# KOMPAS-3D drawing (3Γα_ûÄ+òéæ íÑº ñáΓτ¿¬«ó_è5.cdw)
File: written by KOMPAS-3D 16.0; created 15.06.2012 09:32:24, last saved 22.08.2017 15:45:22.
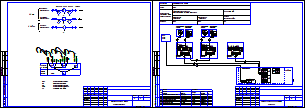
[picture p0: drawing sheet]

Sheets 1-2: A3, landscape

Title block, sheet 1: name: г. Москва, ул. Нежинская, д. 14, к.8 (кв. 1 и кв. 2); sheet number: 1; sheets: 27 / 28; sheet format: A3; stored path: D:\Проекты\Лыткарино\ул. Квартал 3А, д.25\710.74 РП.cdw; cell 320: Р
Title block, sheet 2: sheet number: 2

Views: Вид 2, Вид 3, Вид 4, Вид 5
Referenced files in C:\Program Files (x86)\ASCON\KOMPAS-3D V16\Sys\: SPDS.lcs, EngSys.lcs, GRAPHIC.LHS
Referenced files: graphic.tdp
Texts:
  МО, Клинский район, д. Решетниково, ул. Центральная, д.14
  GOST Common
  Normal
  List Paragraph
  heading 3
  для схемы
  txt
  краны
  Фоновая заливка
  Т0-элементы
  ВРУ
  каб.
  Начало
  трассы
  Трассы
  Марка
  Проложен
  Датчик температуры (Т1)
  Датчик температуры (Т2)
  Датчик давления (Т1)
  Датчик давления (Т2)
  Изм. модуль (Т2)
  Изм. модуль (Т1)
  Изм. модуль (В1)
  ВРУ 220В, 50 Гц
  ИМ1 УУТЭ
  ИМ2 УУТЭ
  ИМ (Т1)
  СБ МКТС
  FTP
  ПВС
  Конец
  Кол-во и
  сеч. жил
  Длина,
  Преобразователь расхода
  Термопреобразователь
  Преобразователь давления
  Преобразователь цифровой
  Системный блок МКТС
  приборы
  по месту
  шкаф
  учета
  UQIES
  Подающий
  трубопровод
  Обратный
  УУТЭ
  Функциональная схема
  Вводной
  УУХВС
  Агрегат
  Системный блок  МКТС
  Среда
  Вода
  параметра и место
  отбора импульса
  Учет тепловой энергии и
  теплоносителя системы отопления
  отопления
  Узел учета ХВС
  трубопровод ХВС
  ИМ1
  ИМ2
  ИМ3
  Плата подключений
  Pt 100
  Преобразователь
  температуры
  давления
  UP+
  UP-
  ИМП
  Лин
  Измерительный
  модуль М121
  Размеры, параметризация
  сит. план
  подача ГВС
  обратка ГВС
  хвс
  обратка
  POLYLINE_STYLE_0.25_RGB_0_0_0
  стены
  Основная (не является границей для штриховки)
  POLYLINE_STYLE_0.18_RGB_0_0_0
  ХВС
  зеленая
  Красная тонкая
  арматура
  Подача
  Скрытая линия
  Ось Z
  Ось Y
  Ось X
  Образующая трубопровода (проектируемого)
  Трубопровод толщиной 0.6мм (одна линия)
  Трубопровод толщиной 1.2мм (одна линия)
  Трубопровод толщиной 1.0мм (одна линия)
  Трубопровод толщиной 0.8мм (одна линия)
  Трубопровод существующий (одна линия)
  Трубопровод невидимый (одна линия)
  Трубопровод демонтируемый (одна линия)
  Осевая трубопровода
  Осевая трубопровода (демонтируемого)
  Образующая трубопровода (существующего)
  Образующая трубопровода (невидимого)
  Изолированный трубопровод проектируемый (одна линия)
  Изолированный трубопровод существующий (одна линия)
  Образующая изоляции
  Изоляция
  Изолированный трубопровод невидимый (одна линия)
  Штрих пвс 075
  штрих пвс 2,5
  существующее оборудование
  Существующее оборудование
  K5LT_BASIC_RGB_0_0_255_THICK_0.53
  POLYLINE_STYLE_1.51_RGB_0_0_255
  POLYLINE_STYLE_0.50_RGB_128_128_128
  K5LT_AXLED_RGB_255_128_0_SC_1_THICK_0.18
  ACAD_ISO04W100_RGB_0_0_0_SC_1_THICK_0.18
  тонкая черная
  пломбировка
  Провода
  синий штрих
  Стили документа
  G2co
  расход вторичной воды объемный
  расход вторичной воды объемный при 70гр
  Gco
  расход теплоносителя массовый
  расход теплоносит объемн подающ
  расход теплоносит объемн обр
  Лапир
  Ghvs
  Im1
  Im2
  Im3
  Im4
  Im5
  Khvs
  норматив ХВС
  число подъездов
  число этажей
  Nkv
  число квартир
  тепловая нагрузка на отопление
  сумма Q
  Qgvs
  тепловая нагрузка ГВС
  тепловая нагрузка на циркуляцию ГВС
  иммитовставка или под манометр
  ro1
  ro2
  ro3
  ro4
  верх предел темп граф
  нижн предел темп граф
  темп подачи ГВС
  темп обр ГВС
  темр хол воды
  vzdh
  Kchn
  Ktp
  Knp
  beta
  tnv
  Vклап
  KLP
  RPD
  RDS
  PUMP
  ro5
  Переход К-76 x 3-38 x 2-09Г2С ГОСТ 17378-2001
  Переход ГОСТ 17378-2001
  Переход
  ГОСТ
  Сталь 09Г2С ГОСТ 19281-89
  Переход К-76 x 3-45 x 2,5-09Г2С ГОСТ 17378-2001
  Переход К-57 x 3-38 x 2-09Г2С ГОСТ 17378-2001
  Переход К-57 x 3-32 x 2-09Г2С ГОСТ 17378-2001
  Втулка 20x50
  Переход К-108 x 4-57 x 3-09Г2С ГОСТ 17378-2001
  Переход К-45 x 2,5-32 x 2-09Г2С ГОСТ 17378-2001
  Переход К-89 x 3,5-45 x 2,5-09Г2С ГОСТ 17378-2001
  Переход К-133 x 5-108 x 4-09Г2С ГОСТ 17378-2001
  Переход К-159 x 4,5-89 x 3,5-09Г2С ГОСТ 17378-2001
  Переход К-45 x 2,5-38 x 2-09Г2С ГОСТ 17378-2001
  Фланец 1-32-1 Ст3сп ГОСТ 12820-80
  Фланцы
  Фланец
  квадратный
  Ст3сп
  Ст3сп ГОСТ 380-2005
  Переход К-57 x 3-45 x 2,5-09Г2С ГОСТ 17378-2001
  Переход К-76 x 3-57 x 3-09Г2С ГОСТ 17378-2001
  Фланец 1-50-16 Ст3сп ГОСТ 12821-80
  Переход К-89 x 3,5-76 x 3,5-09Г2С ГОСТ 17378-2001
  Переход К-108 x 4-89 x 3,5-09Г2С ГОСТ 17378-2001
  Тройник 159 x 4,5-09Г2С ГОСТ 17376-2001
  Тройники ГОСТ 17376-2001
  Тройник
  Отвод 90-159 x 4-09Г2С ГОСТ 17375-2001
  Отвод ГОСТ 17375-2001
  Отвод
  Переход К-108 x 4-76 x 3,5-09Г2С ГОСТ 17378-2001
  Переход К-159 x 4,5-108 x 4-09Г2С ГОСТ 17378-2001
  Переход К-133 x 5-76 x 3,5-09Г2С ГОСТ 17378-2001
  Переход К-133 x 4-89 x 3,5-09Г2С ГОСТ 17378-2001
  Переход К-1-42,4 x 2,6-21,3 x 2-TS10 ГОСТ 17378-2001
  TS10
  Сталь TS10 ИСО 2604/2-75
  Фланец 1-20-16 Ст3сп ГОСТ 12820-80
  Лит-Масса-Масштаб
  Материал-Предприятие
  Title Specification
  Body Specification ( left align )
  Body Specificaton ( centered )
  Поз.
  Кол.
  Приме-
  чание
  Таблица спецификации
  Засыпка
  Штрих3
  Штрих2
  Штрих1
  Песок
  Штр0.5пр7
  Штр0.5пр12
  Штр0.3пр10
  Штр1.4пр21.21
  Штр1пр15
  Штр2.12пр35
  Штр1.5пр25
  Штр2.82пр42.42
  Штр2пр30
  SACNCR_ISO 1
  Электрощитовая
  Пр-1
  Ок-1
  вапвыапвы
  Обозначение стандарта
  Типоразмер
  Разраб.
  Пров.
  Т.контр.
  Н.контр.
  Утв.
  автоматизации
  Рабочие чертежи основного комплекта. ГОСТ Р 21.1101-2009 Ф3
  Стадия
  Лист
  Листов
  Изм.
  Кол.уч.
  №док.
  Подп.
  Дата
  Изменение
  Номер документа
  Подпись
  Наименование объекта строительства, в состав которого входит здание, наим. микр
  Наименование здания (сооружения)
  Порядковый номер листа
  Количество листов в документе
  Наименование изображения
  Индекс предприятия, выпускающего документ
  Инв. № подл.
  Подп. и дата
  Взам. инв. №
  Инвентарный номер подлинника
  Подпись принявшего подлинник на хранение
  Инвентарный номер подлинника, взамен которого выпущен данный подлинник
  Согласовано
  Формат листа
  Согласование
  03 Рабочие чертежи основного комплекта. ГОСТ Р 21.1101-2009 Ф3
  Схема соединений внешних
  проводок
Dimensions and other numbers on the sheet: 0; 220В; 50Гц; 2x2x0,52; 3х0,75; 1; 2; 15; 14; 25; 11; 1,2,3; 4,5; 6,7; 8,9,10; 6; 5; 4; 3; 7; 8; 9; 10; 4,0; 2,6582; 0,0160; 16; 95; 2,6160; 3,0; 70; 0,0000; 4-20; 09Г2С; 12; 17; 19; 20; 21; 22; 23; 24; 26; 30; 31; 33; 34; 52; 64; 65; 66; 67; 69; 71; 72; 73; 74; 75; 27; 28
